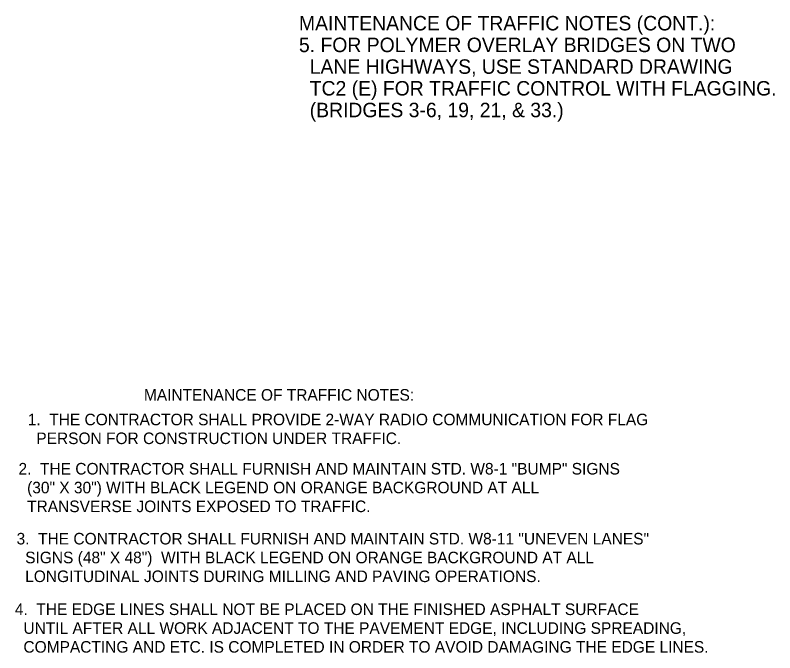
# Model space of a CAD drawing. Extents: x 1925873 to 1930787, y 596452 to 599617.
# Drawn here: x 1928317.8 to 1928711.3, y 597557.3 to 597887.8 of the extents above; entities that cross this region are included whole.
import ezdxf

# ---------------------------------------------------------------- set-up
doc = ezdxf.new("R2010")
doc.units = 0
doc.layers.add('R_Border', color=7, linetype='Continuous')

msp = doc.modelspace()

# ---------------------------------------------------------------- texts
at = {"layer": 'R_Border'}
for s, height, p in [('MAINTENANCE OF TRAFFIC NOTES (CONT.): ', 7.5, (1928464.82, 597879.93)), ('5. FOR POLYMER OVERLAY BRIDGES ON TWO', 7.5, (1928464.82, 597868.68)), ('  LANE HIGHWAYS, USE STANDARD DRAWING', 7.5, (1928464.82, 597857.43)), ('  TC2 (E) FOR TRAFFIC CONTROL WITH FLAGGING.  ', 7.5, (1928464.82, 597846.18)), ('  (BRIDGES 3-6, 19, 21, & 33.)', 7.5, (1928464.82, 597834.93)), ('MAINTENANCE OF TRAFFIC NOTES:', 6, (1928384.52, 597688)), ('1.  THE CONTRACTOR SHALL PROVIDE 2-WAY RADIO COMMUNICATION FOR FLAG ', 6, (1928324.33, 597675.24)), ('  PERSON FOR CONSTRUCTION UNDER TRAFFIC.', 6, (1928324.33, 597665.49)), ('2.  THE CONTRACTOR SHALL FURNISH AND MAINTAIN STD. W8-1 "BUMP" SIGNS', 6, (1928319.56, 597649.72)), ('  (30" X 30") WITH BLACK LEGEND ON ORANGE BACKGROUND AT ALL ', 6, (1928319.56, 597639.97)), ('  TRANSVERSE JOINTS EXPOSED TO TRAFFIC.', 6, (1928319.56, 597630.22)), ('3.  THE CONTRACTOR SHALL FURNISH AND MAINTAIN STD. W8-11 "UNEVEN LANES" ', 6, (1928318.57, 597613.46)), ('  SIGNS (48" X 48")  WITH BLACK LEGEND ON ORANGE BACKGROUND AT ALL ', 6, (1928318.57, 597603.71)), ('  LONGITUDINAL JOINTS DURING MILLING AND PAVING OPERATIONS.', 6, (1928318.57, 597593.96)), ('4.  THE EDGE LINES SHALL NOT BE PLACED ON THE FINISHED ASPHALT SURFACE', 6, (1928317.66, 597576.87)), ('  UNTIL AFTER ALL WORK ADJACENT TO THE PAVEMENT EDGE, INCLUDING SPREADING,', 6, (1928317.66, 597567.12)), ('  COMPACTING AND ETC. IS COMPLETED IN ORDER TO AVOID DAMAGING THE EDGE LINES.', 6, (1928317.66, 597557.37))]:
    msp.add_text(s, height=height, rotation=360, dxfattribs=at).set_placement(p)

doc.saveas('drawing.dxf')
